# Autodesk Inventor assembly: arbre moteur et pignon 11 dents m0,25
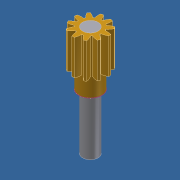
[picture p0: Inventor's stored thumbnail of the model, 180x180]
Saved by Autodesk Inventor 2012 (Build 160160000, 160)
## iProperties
Created: 2011-10
Part Number: arbre moteur et pignon 11 dents m0,25
Document SubType Name: Assembly
Designer: Laur
Author: Laur
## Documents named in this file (3)
- D:\Formulaire\Sujet CIM 2012\Modélisation_7970_shimano\arbre moteur et pignon 11 dents m0,25.iam
- D:\Formulaire\Sujet CIM 2012\Modélisation_7970_shimano\arbre moteur.ipt
- D:\Formulaire\Sujet CIM 2012\Modélisation_7970_shimano\arbre moteur et pignon 11 dents m0,25\Design Accelerator\Engrenages cylindriques1.iam
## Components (2 placed, 2 different names)
1. arbre moteur:1 — Placage:1
2. Engrenages cylindriques:1 [sub-assembly] — Placage:1
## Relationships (1: Mate 1)
- Placage:1 [Mate]: arbre moteur:1 ↔ Engrenages cylindriques:1
